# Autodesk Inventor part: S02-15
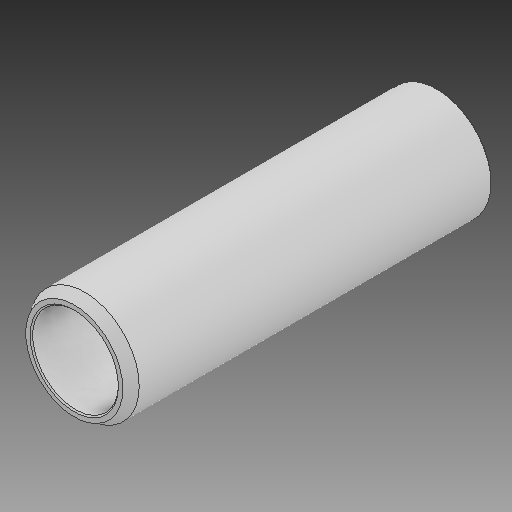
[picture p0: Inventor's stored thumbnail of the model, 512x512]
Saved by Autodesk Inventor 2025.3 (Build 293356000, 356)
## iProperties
Created: 2025-04
Part Number: S02-15
Material: Všeobecné
Document SubType Name: Modeling
Designer: Patrik
Density: 1 g/cm^3
Appearance: Výchozí
Description: Centrovací pouzdro se dvěma lícovacími průměry
Stock Number: E 1160/42x140
User Status: 1.7131
Author: Patrik
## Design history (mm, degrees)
feature "Base1"
feature "Závit1" dims "d0" = 8.418, "d1" = 0
node "Těleso1"
